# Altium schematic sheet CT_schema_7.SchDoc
size 278 x 170 mm
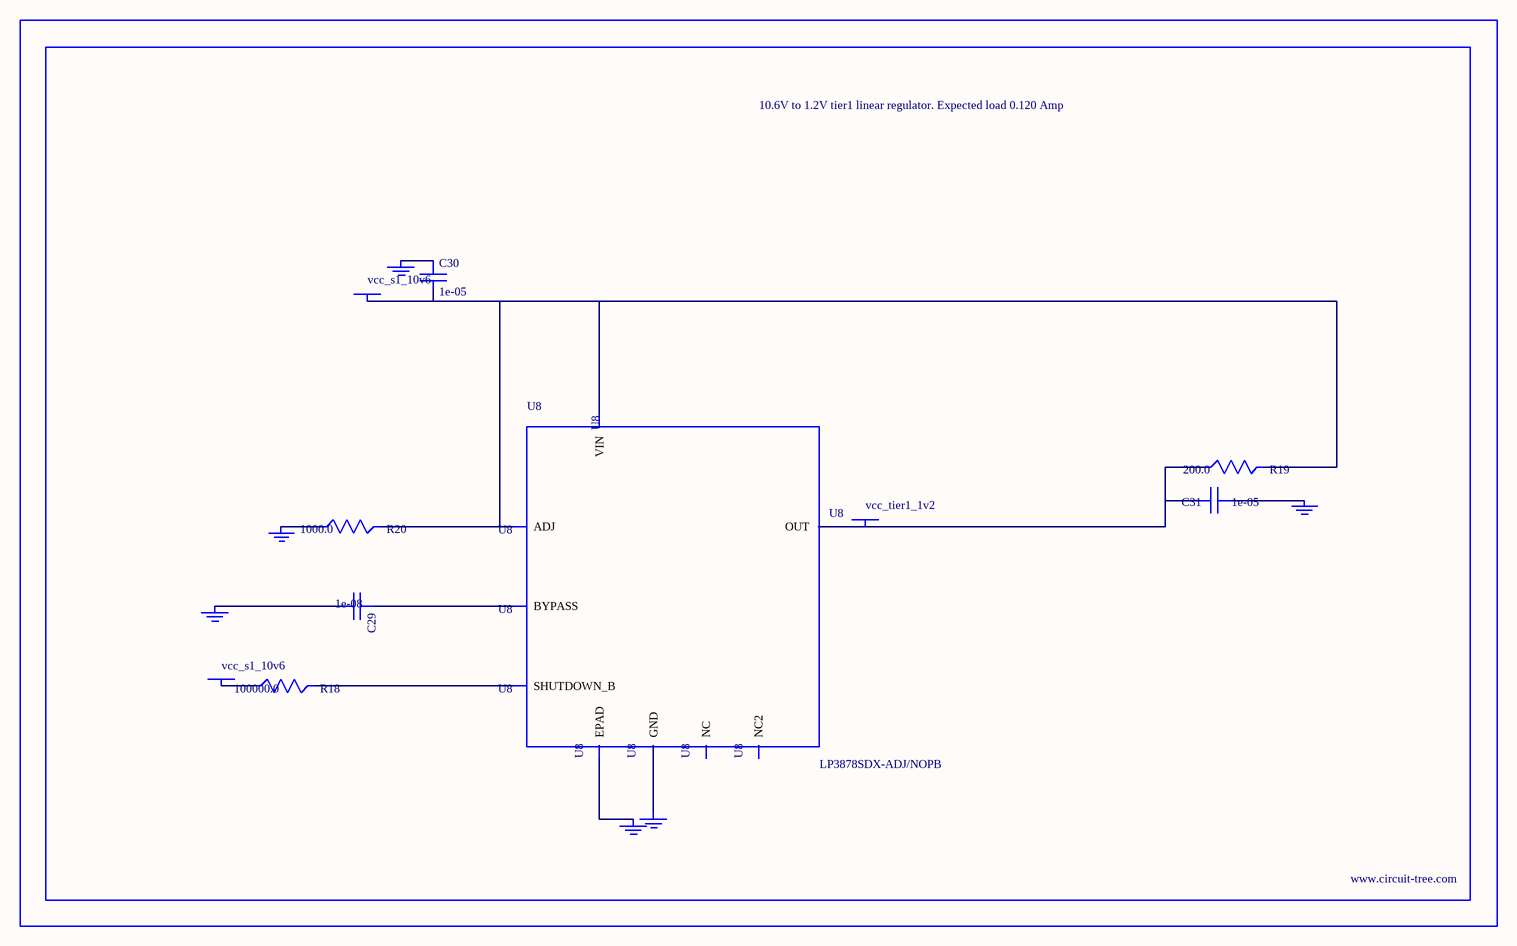
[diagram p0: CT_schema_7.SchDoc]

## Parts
BORDER6  (no value)
C29  1e-08  [C0402]
C30  1e-05  [C1206]
C31  1e-05  [C0805]
GND_INSTANCE_6_0  (no value)
GND_INSTANCE_6_1  (no value)
GND_INSTANCE_6_2  (no value)
GND_INSTANCE_6_3  (no value)
GND_INSTANCE_6_4  (no value)
GND_INSTANCE_6_5  (no value)
POWER_INSTANCE_6_0  vcc_s1_10v6
POWER_INSTANCE_6_1  vcc_s1_10v6
POWER_INSTANCE_6_2  vcc_tier1_1v2
R18  100000.0  [R0603]
R19  200.0  [R0603]
R20  1000.0  [R0603]
U8  LP3878SDX-ADJ/NOPB  [WSON-8]

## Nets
NetC29_1: C29.1 U8.1(BYPASS)
NetC29_2: C29.2 GND_INSTANCE_6_0.0(GND)
NetC30_1: C30.1 GND_INSTANCE_6_1.0(GND)
NetC30_2: C30.2 POWER_INSTANCE_6_0.0(PWR) R19.2 R20.2 U8.4(VIN) U8.6(ADJ)
NetC31_1: C31.1 GND_INSTANCE_6_2.0(GND)
NetC31_2: C31.2 POWER_INSTANCE_6_2.0(PWR) R19.1 U8.5(OUT)
NetGND_INSTANCE_6_3_0: GND_INSTANCE_6_3.0(GND) R20.1
NetGND_INSTANCE_6_4_0: GND_INSTANCE_6_4.0(GND) U8.PAD(EPAD)
NetGND_INSTANCE_6_5_0: GND_INSTANCE_6_5.0(GND) U8.3(GND)
NetPOWER_INSTANCE_6_1_0: POWER_INSTANCE_6_1.0(PWR) R18.1
NetR18_2: R18.2 U8.8(SHUTDOWN_B)

Not connected (* = marked no-connect by the designer): U8 2(NC) 7(NC2)

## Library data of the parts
BORDER6 = BORDER_PAGE6
C29 = C0402C103K3RAC
C30 = C1206C106K3RACTU
C31 = GRM219R60J106ME19D
GND_INSTANCE_6_0-GND_INSTANCE_6_5 = GND
POWER_INSTANCE_6_0-POWER_INSTANCE_6_2 = PWR
R18 = RC0603JR-07100KL
R19 = RC0603JR-07200RL
R20 = RC0603JR-071KL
